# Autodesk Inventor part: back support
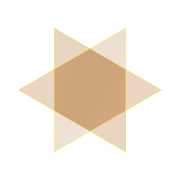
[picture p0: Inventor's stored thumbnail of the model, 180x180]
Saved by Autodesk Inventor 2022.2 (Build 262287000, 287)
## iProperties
Created: 2022-01
Part Number: back support
Material: アルミニウム 6061
Document SubType Name: Sheet Metal
Designer: taeku
Density: 2.7 g/cm^3
Sheet Metal Rule: Default_mm
Appearance: アルミニウム - フラット
Author: taeku
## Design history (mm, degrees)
other parameters: "Thickness" = 1 (derived), "BendRadius" = 1 (= Thickness), "BendReliefWidth" = 1 (= Thickness), "BendReliefDepth" = 0.5 (= 0.5 x Thickness), "CornerReliefSize" = 4 (= 4 x Thickness), "SeamGap" = 0.01, "MinimumRemnant" = 2 (= 2 x Thickness), "TransitionRadius" = 1 (= BendRadius), "JacobiRadiusSize" = 1 (= BendRadius), "GapSize" = 1 (= Thickness)
